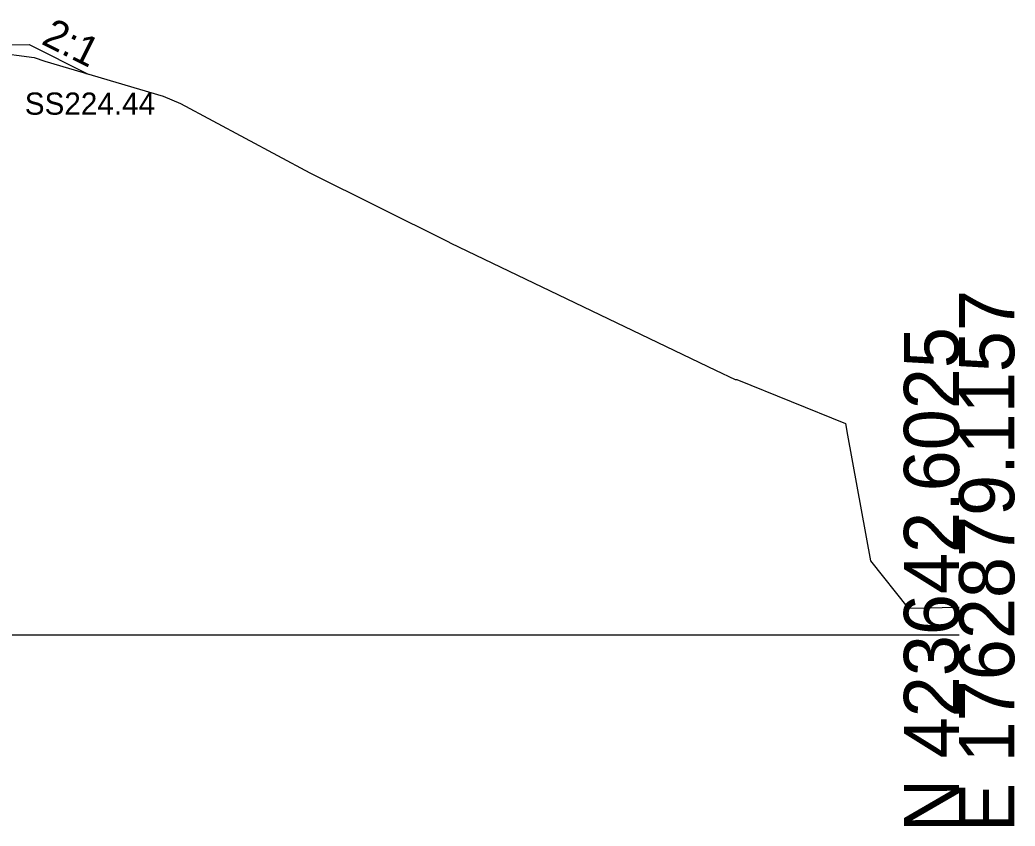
# Model space of a CAD drawing. Extents: x -26 to 3203, y -11010 to 4024.
# Drawn here: x 1152.4 to 1202.8, y -1509.7 to -1468.8 of the extents above; entities that cross this region are included whole.
import ezdxf

# ---------------------------------------------------------------- set-up
doc = ezdxf.new("R2010")
doc.units = 0
for name, color, linetype in [('Exist Cross Section Cell', 7, 'Continuous'), ('Exist XS Ground Line', 7, 'Continuous'), ('Prop CMT Slope Grass', 7, 'Continuous'), ('Prop XS Side Slope Text', 7, 'Continuous'), ('Prop XS SS Elevation Text', 7, 'Continuous'), ('Scratch_Level_0', 7, 'Continuous')]:
    doc.layers.add(name, color=color, linetype=linetype)

msp = doc.modelspace()

# ---------------------------------------------------------------- linework, layer by layer
at = {"layer": 'Exist Cross Section Cell'}
msp.add_line((1100, -1500), (1200, -1500), dxfattribs=at)
at = {"layer": 'Exist XS Ground Line'}
msp.add_lwpolyline([(1151.041, -1470.455), (1153.101, -1470.724), (1153.639, -1470.915), (1159.651, -1472.689), (1160.524, -1473.054), (1167.078, -1476.573), (1174.082, -1480.055), (1174.237, -1480.131), (1187.641, -1486.569), (1188.65, -1487.052), (1188.726, -1487.044), (1194.234, -1489.275), (1194.335, -1489.877), (1195.508, -1496.247), (1197.411, -1498.636), (1200, -1498.597)], dxfattribs=at)
msp.add_lwpolyline([(1151.041, -1470.455), (1153.101, -1470.724), (1153.639, -1470.915), (1159.651, -1472.689), (1160.524, -1473.054), (1167.078, -1476.573), (1174.082, -1480.055), (1174.237, -1480.131), (1187.641, -1486.569), (1188.65, -1487.052), (1188.726, -1487.044), (1194.234, -1489.275), (1194.335, -1489.877), (1195.508, -1496.247), (1197.411, -1498.636), (1200, -1498.597)], dxfattribs=at)
msp.add_lwpolyline([(1151.041, -1470.455), (1153.101, -1470.724), (1153.639, -1470.915), (1159.651, -1472.689), (1160.524, -1473.054), (1167.078, -1476.573), (1174.082, -1480.055), (1174.237, -1480.131), (1187.641, -1486.569), (1188.65, -1487.052), (1188.726, -1487.044), (1194.234, -1489.275), (1194.335, -1489.877), (1195.508, -1496.247), (1197.411, -1498.636), (1200, -1498.597)], dxfattribs=at)
msp.add_lwpolyline([(1151.041, -1470.455), (1153.101, -1470.724), (1153.639, -1470.915), (1159.651, -1472.689), (1160.524, -1473.054), (1167.078, -1476.573), (1174.082, -1480.055), (1174.237, -1480.131), (1187.641, -1486.569), (1188.65, -1487.052), (1188.726, -1487.044), (1194.234, -1489.275), (1194.335, -1489.877), (1195.508, -1496.247), (1197.411, -1498.636), (1200, -1498.597)], dxfattribs=at)
msp.add_lwpolyline([(1151.041, -1470.455), (1153.101, -1470.724), (1153.639, -1470.915), (1159.651, -1472.689), (1160.524, -1473.054), (1167.078, -1476.573), (1174.082, -1480.055), (1174.237, -1480.131), (1187.641, -1486.569), (1188.65, -1487.052), (1188.726, -1487.044), (1194.234, -1489.275), (1194.335, -1489.877), (1195.508, -1496.247), (1197.411, -1498.636), (1200, -1498.597)], dxfattribs=at)
at = {"layer": 'Prop CMT Slope Grass'}
msp.add_lwpolyline([(1149.341, -1470.135), (1152.841, -1470.065), (1155.839, -1471.564)], dxfattribs=at)

# ---------------------------------------------------------------- texts
at = {"layer": 'Exist Cross Section Cell'}
for s, p in [('E 1762879.1157', (1202.8, -1510)), ('N 423642.6025', (1200, -1510))]:
    msp.add_text(s, height=2.8, rotation=90, dxfattribs=at).set_placement(p)
at = {"layer": 'Prop XS Side Slope Text'}
msp.add_text('2:1', height=1.5, rotation=333.4349, dxfattribs=at).set_placement((1153.411, -1470.014))
at = {"layer": 'Prop XS SS Elevation Text'}
msp.add_text('SS224.44', height=1.125, dxfattribs=at).set_placement((1152.625, -1473.626))
at = {"layer": 'Scratch_Level_0'}
for s, p in [('RT_CSLP_Pnt', (1152.742, -1470.075)), ('Exterior Boundary', (1155.681, -1471.574)), ('RT_Slope_Fill', (1155.745, -1471.574))]:
    msp.add_text(s, height=0.02, dxfattribs=at).set_placement(p)

doc.saveas('drawing.dxf')
